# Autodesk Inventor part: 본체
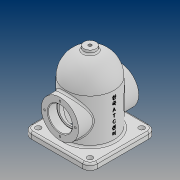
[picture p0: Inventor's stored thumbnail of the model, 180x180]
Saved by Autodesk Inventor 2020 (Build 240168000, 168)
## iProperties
Created: 2021-08
Part Number: 본체
Material: 일반
Document SubType Name: Modeling
Designer: PC312-
Density: 1 g/cm^3
Appearance: 기본값
Mass: 320.706 g
Surface Area: 800.755 cm^2
Volume: 320.706 cm^3
Author: PC312-
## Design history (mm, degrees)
sketch "스케치1"
  geometry: C1 r 40 at (0, 0); 1 further point
  constraints: 1 centre point, 1 coincident
  dimensions: "d0" = 80 diameter of C1
extrude "돌출1" new body sketch "스케치1" distance "d1" = 36; taper "d3" = 0 deg; dims "d2" = 48, "d4" = 0
node "작업 평면1"
sketch "스케치4"
  geometry: C1 r 40 at (0, 0) reference; 1 further point
extrude "돌출4" join sketch "스케치4" distance "d15" = 40; taper "d16" = 0 deg
fillet "모깎기2" dims "d17" = 40
feature "쉘2" dims "d25" = 8
sketch "스케치7"
  geometry: C1 r 31 at (0, 0); 1 further point
  constraints: 1 centre point, 1 coincident
  dimensions: "d26" = 62 diameter of C1
extrude "돌출5" join sketch "스케치7" stored distance "d27" = 40; taper "d28" = 0 deg
sketch "스케치8"
  geometry: C1 r 31 at (0, 0) reference; 2 further points
  constraints: 1 coincident
hole "구멍2" sketch "스케치8" at (0, 0) diameter "d29" = 33; stored, may be unused: countersink angle "d33" = 90 deg, drill point angle "d35" = 0 deg; dims "d30" = 6, "d31" = 40, "d32" = 15, "d34" = 40
sketch "스케치9"
  geometry: L1 (-55, -55)-(55, -55); L2 (55, -55)-(55, 55); L3 (55, 55)-(-55, 55); L4 (-55, 55)-(-55, -55); L5 (-55, -55)-(55, 55); L6 (55, -55)-(-55, 55); C1 r 40 at (0, 0) reference; 1 further point
  constraints: 12 end point, 2 midpoint, 2 parallel, 1 horizontal, 1 perpendicular
  dimensions: "d36" = 110 distance of L3.end L2.end; "d37" = 110 distance of L2.end L1.end
extrude "돌출6" join sketch "스케치9" distance "d38" = 10; taper "d39" = 0 deg
node "작업 평면2"
sketch "스케치10"
  geometry: C1 r 10 at (0, 0); 1 further point
  constraints: 1 centre point, 1 coincident
  dimensions: "d41" = 20 diameter of C1
extrude "돌출7" join sketch "스케치10" stored distance "d42" = 10; taper "d43" = 0 deg
sketch "스케치11"
  geometry: C1 r 10 at (0, 0) reference; 2 further points
  constraints: 1 coincident
hole "구멍3" sketch "스케치11" at (0, 0) diameter "d44" = 5.1881; stored, may be unused: countersink angle "d48" = 90 deg, drill point angle "d50" = 0 deg; dims "d45" = 20, "d46" = 40, "d47" = 15, "d49" = 20
sketch "스케치12"
  geometry: 2 further points
  constraints: 1 vertical alignment
  dimensions: "d51" = 25.5 distance of point (0, 0) point (0, 25.5)
hole "구멍4" sketch "스케치12" at (0, 25.5) diameter "d52" = 3.242; stored, may be unused: countersink angle "d56" = 90 deg, drill point angle "d58" = 118 deg; dims "d53" = 8, "d54" = 40, "d55" = 15, "d57" = 10
fillet "모깎기3" dims "d62" = 12
fillet "모깎기4" dims "d63" = 0.3
fillet "모깎기5" dims "d64" = 3
fillet "모깎기6" dims "d65" = 3
chamfer "모따기1" distance "d66" = 1; stored, may be unused: second distance "d67" = 2, angle "d68" = 45 deg
chamfer "모따기2" distance "d69" = 1; stored, may be unused: second distance "d70" = 2, angle "d71" = 45 deg
node "작업 평면3"
sketch "스케치13"
  geometry: L1 (-48, -43)-(-48, 43) reference; 2 further points
  constraints: 1 coincident, 1 other
  dimensions: "d73" = 48 distance from line of L1 point (0, 0)
feature "엠보싱1" sketch "스케치13" dims "d74" = 0.5, "d75" = 0
sketch "스케치14"
  geometry: A1 r 12 centre (-43, -43) between (-55, -43) and (-43, -55) reference; A2 r 12 centre (-43, 43) between (-43, 55) and (-55, 43) reference; A3 r 12 centre (43, 43) between (55, 43) and (43, 55) reference; A4 r 12 centre (43, -43) between (43, -55) and (55, -43) reference; 5 further points
  constraints: 4 coincident
hole "구멍5" sketch "스케치14" at (43, -43), (-43, 43), (-43, -43), (43, 43) diameter "d76" = 9; stored, may be unused: countersink angle "d80" = 90 deg, drill point angle "d82" = 0 deg; dims "d77" = 8, "d78" = 40, "d79" = 15, "d81" = 10
node "솔리드1"
mirror "미러1"
pattern_circular "원형 패턴1" dims angle "d60" = 360 deg
mirror "미러2"
feature "A9D066F2-1C7D-4E18-AEED-F7BC21143FA4" dims "d29" = 33, "d30" = 6, "d31" = 40, "d32" = 15, "d33" = 90 deg, "d34" = 40, "d35" = 0
other parameters: "d40" = -129
